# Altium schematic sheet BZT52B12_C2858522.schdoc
size 127 x 101 mm
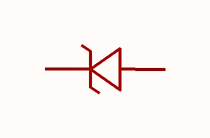
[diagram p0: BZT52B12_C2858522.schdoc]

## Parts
D?  bzt52b12_c2858522  [SOD-123F_L2.7-W1.7-LS3.7-RD]  (value not drawn)

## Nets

Not connected (* = marked no-connect by the designer): D? 1(C) 2(A)

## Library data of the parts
D? = bzt52b12_c2858522: 二极管配置:1个独立式;稳压值(标称值):12V;稳压值(范围值):11.76V~12.24V;耗散功率(Pd):500mW;; Manufacturer: MDD(辰达半导体); AddInBom: yes; ModelId: f89b7cbf535a4ec284505f5b478c5a5a; ModelTransform: 147.6375,64.961,0,0,0,0,0,0,0; Diode Configuration: 1个独立式; Zener Voltage(Nom): 12V; Reverse Leakage Current (Ir): 100nA@9V; Pd - Power Dissipation: 500mW; Impedance(Zzt): 35Ω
